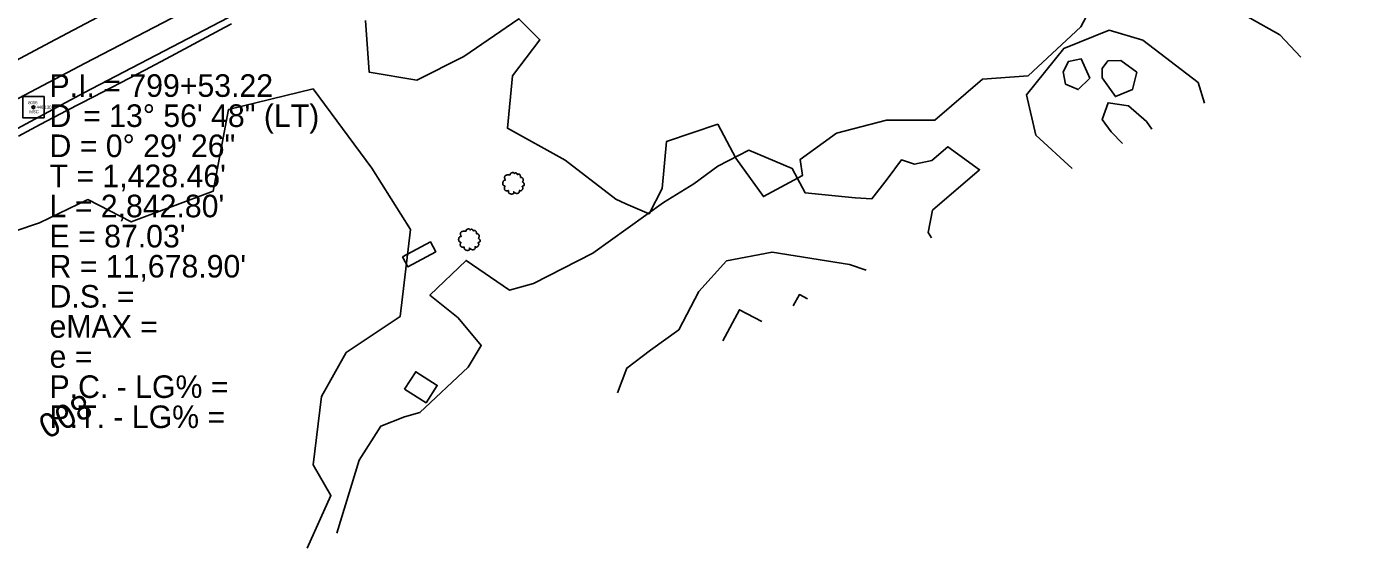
# Model space of a CAD drawing. Extents: x 1901471 to 1963503, y 756461 to 799997.
# Drawn here: x 1904480.4 to 1904919.9, y 758248 to 758423.4 of the extents above; entities that cross this region are included whole.
import ezdxf

# ---------------------------------------------------------------- set-up
doc = ezdxf.new("R2010")
doc.units = 0
for name, color, linetype in [('RD_DTM_BkLn1', 7, 'Continuous'), ('RD_EX_Bldg', 7, 'Continuous'), ('RD_EX_Driveway', 7, 'Continuous'), ('RD_EX_Road', 7, 'Continuous'), ('RD_EX_Road_txCode', 7, 'Continuous'), ('RD_EX_VEG', 7, 'Continuous'), ('RD_HC_Cl', 7, 'Continuous'), ('RD_HC_Data', 7, 'Continuous'), ('RD_HC_Survey', 7, 'Continuous'), ('RD_HC_TX_Sta50', 7, 'Continuous'), ('RD_HC_txCode', 7, 'Continuous'), ('RD_SMD_Locator', 7, 'Continuous')]:
    doc.layers.add(name, color=color, linetype=linetype)

# ---------------------------------------------------------------- blocks, each defined once
blk = doc.blocks.new('T2')
at = {"layer": 'RD_EX_VEG'}
for points in [[(0.05233333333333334, 7.213166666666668), (-0.24750000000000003, 7.238166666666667), (-0.5723333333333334, 7.138166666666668), (-0.8222500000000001, 7.038250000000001), (-1.0471666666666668, 6.963250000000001), (-1.2720833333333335, 6.863250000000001), (-1.5719166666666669, 6.688416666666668), (-1.7968333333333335, 6.488416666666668), (-1.9218333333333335, 6.2385833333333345), (-1.9718333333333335, 6.013666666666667), (-2.0217500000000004, 5.738833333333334), (-2.0217500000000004, 5.563833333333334), (-2.146666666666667, 5.538833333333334), (-2.296666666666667, 5.563833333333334), (-2.5465000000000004, 5.638833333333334), (-2.796416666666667, 5.638833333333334), (-3.0463333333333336, 5.638833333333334), (-3.3961666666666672, 5.613833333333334), (-3.7460000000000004, 5.613833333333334), (-4.020833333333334, 5.563833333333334), (-4.345750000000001, 5.513916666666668), (-4.720583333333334, 5.389000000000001), (-5.0704166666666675, 5.264000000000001), (-5.37025, 5.014083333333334), (-5.620166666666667, 4.539333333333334), (-5.745166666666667, 4.189500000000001), (-5.895083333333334, 3.9395833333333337), (-5.745166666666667, 3.489833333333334), (-5.570166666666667, 3.139916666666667), (-5.545250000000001, 2.9400000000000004), (-5.470250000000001, 2.5152500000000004), (-5.37025, 2.2903333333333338), (-5.245333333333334, 2.0903333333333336), (-5.320250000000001, 2.065416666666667), (-5.695166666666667, 2.015416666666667), (-5.995000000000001, 1.9155000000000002), (-6.419833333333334, 1.6905833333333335), (-6.644750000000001, 1.465666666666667), (-6.744750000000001, 1.1407500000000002), (-6.769666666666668, 0.7909166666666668), (-6.869583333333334, 0.5910833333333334), (-6.944583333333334, 0.3161666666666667), (-6.969583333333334, 0.2411666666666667), (-7.019583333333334, -0.08366666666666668), (-6.9195833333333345, -0.5335000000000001), (-6.894583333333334, -0.8833333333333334), (-6.769666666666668, -1.1082500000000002), (-6.619750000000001, -1.2830833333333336), (-6.444833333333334, -1.5330000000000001), (-6.045000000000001, -1.7579166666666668), (-5.7201666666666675, -1.8579166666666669), (-5.520250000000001, -1.8828333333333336), (-5.695166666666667, -2.382666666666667), (-5.745166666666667, -2.7325000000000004), (-5.870083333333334, -3.132333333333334), (-5.870083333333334, -3.2072500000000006), (-5.920000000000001, -3.682083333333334), (-5.770166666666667, -4.007000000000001), (-5.695166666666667, -4.38175), (-5.520250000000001, -4.606666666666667), (-5.245333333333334, -4.906583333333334), (-4.9205000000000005, -5.131416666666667), (-4.420666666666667, -5.256416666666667), (-4.020833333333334, -5.231416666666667), (-3.4460833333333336, -5.056500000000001), (-3.1962500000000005, -4.9815000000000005), (-3.2212500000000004, -5.156416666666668), (-3.1962500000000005, -5.531333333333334), (-3.1962500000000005, -5.956083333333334), (-3.0463333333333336, -6.280916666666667), (-2.946333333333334, -6.555833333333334), (-2.796416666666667, -6.805750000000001), (-2.4715000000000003, -7.030583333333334), (-2.07175, -7.1055833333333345), (-1.6469166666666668, -7.2555000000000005), (-1.1970833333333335, -7.330500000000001), (-0.6973333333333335, -7.355500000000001), (-0.09758333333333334, -7.205583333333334), (0.17725000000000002, -7.080583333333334), (0.27725000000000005, -6.905666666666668), (0.47716666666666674, -6.530833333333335), (0.4271666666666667, -6.3059166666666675), (0.4521666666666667, -5.706166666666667), (0.5520833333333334, -5.881166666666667), (0.7270833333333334, -6.231000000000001), (1.2268333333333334, -6.530833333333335), (1.626666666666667, -6.705750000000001), (2.101416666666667, -6.8557500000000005), (2.4013333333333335, -6.930666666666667), (2.8760833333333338, -6.8557500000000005), (3.2510000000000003, -6.780750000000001), (3.6257500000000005, -6.655750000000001), (3.9256666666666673, -6.380916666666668), (4.100583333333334, -6.106000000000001), (4.1505833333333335, -5.831166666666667), (4.2255, -5.456333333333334), (4.275500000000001, -5.281416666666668)], [(4.275500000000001, -5.281416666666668), (4.200583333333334, -5.106416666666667), (4.1505833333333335, -4.856583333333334), (4.2255, -4.881583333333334), (4.4004166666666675, -4.931583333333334), (4.675333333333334, -5.056500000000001), (4.900250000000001, -5.131416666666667), (5.225083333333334, -5.106416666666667), (5.500000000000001, -5.006500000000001), (5.949750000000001, -4.731583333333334), (6.224666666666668, -4.256833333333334), (6.499500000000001, -3.8570000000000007), (6.5745000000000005, -3.5321666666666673), (6.524500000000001, -3.3072500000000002), (6.499500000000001, -2.8075000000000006), (6.299583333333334, -2.5575833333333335), (6.249583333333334, -2.432666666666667), (6.1496666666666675, -2.0328333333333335), (6.224666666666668, -1.9828333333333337), (6.499500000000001, -1.9328333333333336), (6.874333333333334, -1.8079166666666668), (7.149250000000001, -1.6830000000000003), (7.374166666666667, -1.5080000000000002), (7.449083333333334, -1.2830833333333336), (7.424166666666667, -0.8833333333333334), (7.4740833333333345, -0.48350000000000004), (7.399166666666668, -0.3335), (7.299166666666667, -0.1836666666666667), (7.224166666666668, 0.016333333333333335), (7.074250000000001, 0.16616666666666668), (6.974333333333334, 0.3161666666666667), (6.874333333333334, 0.41608333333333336), (6.749416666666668, 0.5660833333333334), (6.5745000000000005, 0.6910000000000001), (6.424583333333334, 0.7410000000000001), (6.374583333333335, 0.8909166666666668), (6.524500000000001, 1.0908333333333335), (6.5745000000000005, 1.1907500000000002), (6.599416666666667, 1.4156666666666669), (6.824416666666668, 1.7655000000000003), (6.874333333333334, 2.1653333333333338), (6.824416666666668, 2.590166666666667), (6.774416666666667, 2.8650833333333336), (6.624416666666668, 3.139916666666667), (6.424583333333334, 3.3898333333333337), (6.299583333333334, 3.5647500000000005), (6.124666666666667, 3.689666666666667), (5.799833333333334, 3.814666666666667), (5.549916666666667, 3.864583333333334), (5.200083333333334, 3.864583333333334), (5.000166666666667, 3.9145833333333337), (5.025166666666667, 3.964583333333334), (5.025166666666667, 4.1145000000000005), (5.025166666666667, 4.389416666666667), (4.950166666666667, 4.839166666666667), (4.800250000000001, 5.339), (4.800250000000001, 5.364000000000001), (4.7002500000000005, 5.613833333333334), (4.475416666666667, 5.813750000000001), (4.3005, 5.913666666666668), (4.100583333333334, 6.038666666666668), (3.850666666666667, 6.063666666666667), (3.5508333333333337, 6.063666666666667), (3.2759166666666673, 6.013666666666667), (3.0760000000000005, 5.913666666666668), (2.9010833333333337, 5.788750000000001), (2.8260833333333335, 5.938666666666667), (2.726166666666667, 6.2385833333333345), (2.676166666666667, 6.3885000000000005), (2.52625, 6.563416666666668), (2.301416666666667, 6.7633333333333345), (1.8515000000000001, 6.888250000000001), (1.2268333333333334, 6.813333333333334), (0.9269166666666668, 6.613416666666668), (0.7770000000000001, 6.438500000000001), (0.7270833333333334, 6.563416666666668), (0.5270833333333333, 6.7633333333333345), (0.4271666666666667, 6.938250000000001), (0.25225000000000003, 7.063250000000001), (0.10233333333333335, 7.163166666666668), (0.0023333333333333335, 7.213166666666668)]]:
    blk.add_spline(points, degree=3, dxfattribs=at)

msp = doc.modelspace()

# ---------------------------------------------------------------- linework, layer by layer
at = {"layer": 'RD_DTM_BkLn1'}
msp.add_lwpolyline([(1904477.7286015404, 758386.9893352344), (1904484.8739688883, 758390.8268119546), (1904493.7516579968, 758395.4295827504), (1904502.6293471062, 758400.0323535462), (1904511.5070362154, 758404.635124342), (1904519.5691333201, 758408.8150392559), (1904528.3776689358, 758413.5474141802), (1904537.1862045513, 758418.2797891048), (1904545.994740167, 758423.0121640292), (1904548.349993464, 758424.277520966)], dxfattribs=at)
at = {"layer": 'RD_EX_Bldg'}
for points in [[(1904605.0800000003, 758346.8600000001), (1904614.3400000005, 758351.8500000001), (1904616.1200000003, 758348.5400000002), (1904606.8600000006, 758343.56)], [(1904605.8000000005, 758302.9500000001), (1904609.4600000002, 758308.7000000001), (1904616.6000000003, 758304.1500000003), (1904612.9400000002, 758298.4100000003)]]:
    msp.add_lwpolyline(points, close=True, dxfattribs=at)
for points in [[(1904734.7400000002, 758330.5400000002), (1904736.7600000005, 758334.3400000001), (1904739.4900000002, 758332.8900000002)], [(1904711.3700000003, 758318.9900000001), (1904716.8700000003, 758329.31), (1904724.2600000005, 758325.3600000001)]]:
    msp.add_lwpolyline(points, dxfattribs=at)
at = {"layer": 'RD_EX_Driveway'}
for points in [[(1904827.2800000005, 758376.2600000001), (1904815.2400000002, 758387.32), (1904812.1200000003, 758400.6400000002), (1904824.4500000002, 758416.08), (1904839.4700000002, 758422.1800000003), (1904850.6600000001, 758418.7800000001), (1904869.0800000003, 758404.7500000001), (1904871.14, 758397.8900000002)], [(1904840.1800000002, 758388.3900000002), (1904837.2000000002, 758392.4900000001), (1904839.1800000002, 758398.0200000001), (1904845.9800000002, 758397.0300000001), (1904851.9400000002, 758391.7900000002), (1904853.6700000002, 758389.3)], [(1904843.9600000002, 758384.5100000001), (1904840.1800000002, 758388.3900000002)], [(1904583.2900000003, 758255.1100000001), (1904590.6800000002, 758279.32), (1904597.8800000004, 758290.6000000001), (1904605.8000000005, 758293.7200000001), (1904610.8400000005, 758295.1600000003), (1904626.9100000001, 758310.2700000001), (1904631.2300000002, 758317.4700000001), (1904623.5600000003, 758326.5900000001), (1904614.2000000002, 758334.1400000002), (1904626.1900000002, 758345.6600000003), (1904640.5900000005, 758335.82), (1904648.5100000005, 758337.9800000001), (1904668.1800000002, 758348.06), (1904691.7000000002, 758364.8600000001), (1904701.7700000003, 758371.0900000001), (1904709.6900000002, 758376.9700000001), (1904720.0100000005, 758382.2500000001), (1904734.4000000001, 758376.2500000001), (1904738.7200000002, 758368.0900000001), (1904755.2800000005, 758366.4200000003), (1904760.8000000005, 758366.1800000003), (1904765.8300000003, 758372.6500000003), (1904770.6300000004, 758379.1300000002), (1904774.9500000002, 758377.6900000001), (1904780.7100000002, 758378.8900000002), (1904785.9900000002, 758383.4500000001), (1904796.5500000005, 758375.7700000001), (1904780.9500000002, 758362.3400000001), (1904779.5100000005, 758354.9000000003), (1904780.6300000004, 758353.2200000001)], [(1904758.8800000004, 758342.4700000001), (1904753.3600000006, 758344.3400000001), (1904727.6900000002, 758348.4200000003), (1904712.5700000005, 758345.5400000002), (1904703.4500000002, 758335.3400000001), (1904696.7300000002, 758322.6300000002), (1904687.3800000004, 758315.9100000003), (1904679.4600000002, 758309.9100000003), (1904676.4600000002, 758301.7500000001)]]:
    msp.add_lwpolyline(points, dxfattribs=at)
for points in [[(1904825.0200000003, 758404.2500000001), (1904824.3100000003, 758408.3600000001), (1904826.0100000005, 758411.7600000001), (1904830.2600000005, 758412.6100000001), (1904833.0900000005, 758406.2400000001), (1904829.2700000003, 758402.4100000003)], [(1904839.0400000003, 758411.9800000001), (1904843.4300000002, 758412.1200000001), (1904848.6800000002, 758408.1500000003), (1904847.2600000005, 758402.4800000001), (1904841.5900000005, 758400.07), (1904837.2000000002, 758406.31), (1904837.2000000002, 758409.4300000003)]]:
    msp.add_lwpolyline(points, close=True, dxfattribs=at)
at = {"layer": 'RD_EX_Road'}
for points in [[(1906146.3600000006, 759121.2900000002), (1905900.2300000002, 759028.4300000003), (1905683.8300000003, 758945.07), (1905509.3000000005, 758874.7600000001), (1905339.14, 758802.9900000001), (1905228.7200000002, 758755.05), (1905125.2300000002, 758708.1700000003), (1905011.4500000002, 758655.7600000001), (1904902.1500000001, 758603.9600000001), (1904794.64, 758551.6600000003), (1904634.6500000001, 758472.0000000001), (1904568.6500000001, 758437.4900000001), (1904499.4200000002, 758401.3400000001), (1904387.3200000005, 758341.0900000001), (1904276.9000000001, 758280.57), (1904172.5200000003, 758222.06), (1904029.7700000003, 758139.2100000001), (1903914.7600000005, 758070.5200000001), (1903832.0800000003, 758019.6100000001), (1903783.8600000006, 757989.9700000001), (1903644.9100000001, 757900.6300000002)], [(1904425.6900000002, 758372.1300000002), (1904499.7700000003, 758411.2400000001), (1904668.8400000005, 758499.2200000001), (1904776.5700000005, 758552.0100000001), (1904918.64, 758621.33), (1905017.7900000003, 758668.5400000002), (1905160.7100000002, 758733.9900000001), (1905269.7300000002, 758782.4900000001), (1905357.7200000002, 758820.05), (1905471.89, 758868.1200000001), (1905613.5200000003, 758924.9900000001), (1905755.5900000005, 758981.6400000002), (1905858.1700000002, 759020.06), (1905901.2500000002, 759036.4900000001), (1906001.5500000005, 759075.3800000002)]]:
    msp.add_lwpolyline(points, dxfattribs=at)
at = {"layer": 'RD_EX_VEG'}
for points in [[(1904840.4500000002, 758442.7100000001), (1904830.14, 758423.2800000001), (1904812.6200000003, 758406.9600000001), (1904797.5100000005, 758405.8800000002), (1904781.6700000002, 758392.2100000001), (1904765.6000000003, 758392.2100000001), (1904749.0400000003, 758387.8900000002), (1904737.0400000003, 758379.2500000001), (1904737.7600000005, 758373.8500000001), (1904724.8100000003, 758366.9000000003), (1904715.6900000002, 758379.6100000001), (1904709.6900000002, 758390.8900000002), (1904692.6600000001, 758385.1300000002), (1904691.2200000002, 758369.5300000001), (1904686.9000000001, 758361.1400000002), (1904679.2200000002, 758364.5000000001), (1904675.8600000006, 758366.06), (1904659.0700000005, 758379.0100000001), (1904639.8700000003, 758389.57), (1904641.5500000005, 758406.9600000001), (1904650.6700000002, 758418.9600000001), (1904643.7100000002, 758425.9200000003), (1904625.4800000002, 758413.4400000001), (1904609.8800000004, 758405.5200000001), (1904594.0400000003, 758408.1600000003), (1904592.8400000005, 758425.32)], [(1904903.1300000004, 758413.1600000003), (1904896.1200000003, 758420.6400000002), (1904876.4400000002, 758431.6800000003)], [(1904460.6600000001, 758350.06), (1904484.6600000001, 758358.2100000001), (1904500.6600000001, 758365.9100000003), (1904515.1000000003, 758358.4500000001), (1904542.2800000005, 758368.6500000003), (1904547.3800000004, 758395.83), (1904575.4200000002, 758402.6300000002), (1904594.9600000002, 758376.2900000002), (1904607.7000000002, 758355.9000000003), (1904604.3000000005, 758327.0200000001), (1904586.3700000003, 758315.07), (1904578.2100000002, 758300.4300000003), (1904575.4200000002, 758277.7500000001), (1904581.3600000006, 758267.55), (1904573.5000000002, 758250.1100000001)]]:
    msp.add_lwpolyline(points, dxfattribs=at)
at = {"layer": 'RD_HC_Cl'}
for centre, radius, start, end in [((1909748.7424915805, 747960.7441562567), 11817.558600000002, 110.89446955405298, 124.79300228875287), ((1909868.3179015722, 747986.8147650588), 11792.712600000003, 110.9034065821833, 124.88102250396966), ((1909948.5939643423, 748094.2795221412), 11678.903500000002, 110.90197060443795, 124.84851962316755)]:
    msp.add_arc(centre, radius, start, end, dxfattribs=at)
at = {"layer": 'RD_HC_Survey'}
msp.add_lwpolyline([(1904486.1855339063, 758400.1075339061), (1904479.1144660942, 758400.1075339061), (1904479.1144660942, 758393.0364660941), (1904486.1855339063, 758393.0364660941)], close=True, dxfattribs=at)
msp.add_circle((1904482.6500000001, 758396.572), 0.5000000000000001, dxfattribs=at)
at = {"layer": 'RD_SMD_Locator'}
msp.add_circle((1904482.6500000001, 758396.572), 0.001, dxfattribs=at)

# ---------------------------------------------------------------- block references
at = {"layer": 'RD_EX_VEG', "xscale": 0.4921259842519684, "yscale": 0.4921259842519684}
for p in [(1904641.7900000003, 758371.33), (1904627.1500000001, 758352.6200000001)]:
    msp.add_blockref('T2', p, dxfattribs=at)

# ---------------------------------------------------------------- texts
at = {"layer": 'RD_EX_Road_txCode'}
msp.add_text('446.130', height=1.0000000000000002, dxfattribs=at).set_placement((1904483.6500000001, 758396.072))
at = {"layer": 'RD_HC_Data'}
for s, p in [('P.I. = 799+53.22', (1904488.0000000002, 758400.0000000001)), ('D', (1904488.0000000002, 758390.0000000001)), ('    = 13%%d 56\' 48" (LT)', (1904488.0000000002, 758390.0000000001)), ('D = 0%%d 29\' 26"', (1904488.0000000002, 758380.0000000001)), ("T = 1,428.46'", (1904488.0000000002, 758370.0000000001)), ("L = 2,842.80'", (1904488.0000000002, 758360.0000000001)), ("E = 87.03'", (1904488.0000000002, 758350.0000000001)), ("R = 11,678.90'", (1904488.0000000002, 758340.0000000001)), ('D.S. = ', (1904488.0000000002, 758330.0000000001)), ('eMAX = ', (1904488.0000000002, 758320.0000000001)), ('e = ', (1904488.0000000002, 758310.0000000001)), ('P.C. - LG% = ', (1904488.0000000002, 758300.0000000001)), ('P.T. - LG% = ', (1904488.0000000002, 758290.0000000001))]:
    msp.add_text(s, height=7.500000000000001, dxfattribs=at).set_placement(p)
at = {"layer": 'RD_HC_TX_Sta50'}
msp.add_text('800', height=8.000000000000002, rotation=208.13939369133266, dxfattribs=at).set_placement((1904499.245971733, 758301.6538438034))
at = {"layer": 'RD_HC_txCode'}
for s, p in [('8005', (1904480.941338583, 758397.572)), ('MSC', (1904481.3350393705, 758394.572))]:
    msp.add_text(s, height=1.0000000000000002, dxfattribs=at).set_placement(p)

doc.saveas('drawing.dxf')
